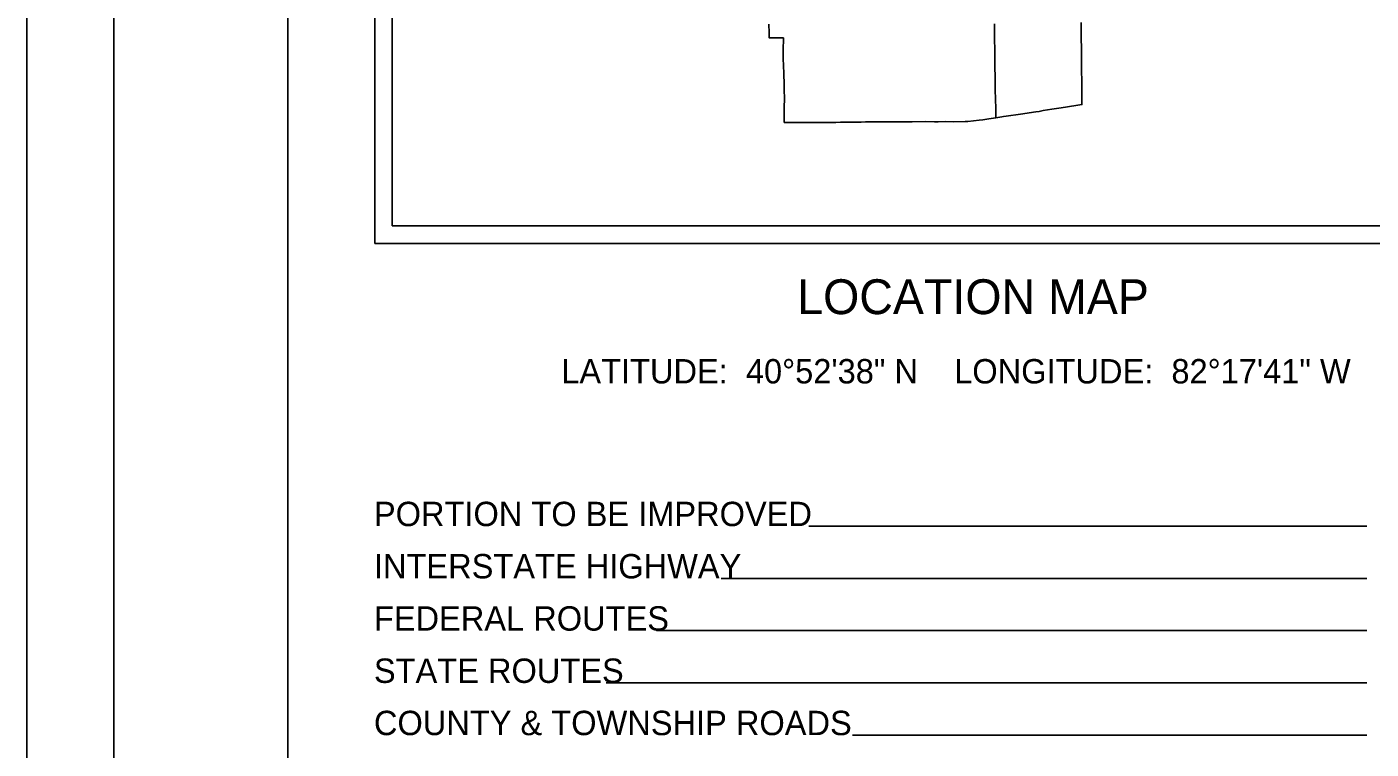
# Model space of a CAD drawing. Extents: x 0 to 34, y 0 to 22.
# Drawn here: x 0 to 7.72, y 11.1 to 15.24 of the extents above; entities that cross this region are included whole.
import ezdxf

# ---------------------------------------------------------------- set-up
doc = ezdxf.new("R2010")
doc.units = 0
for name, color, linetype in [('Default', 7, 'Continuous'), ('SH_Border', 7, 'Continuous'), ('SH_Cut_Line', 7, 'Continuous'), ('SH_Data', 7, 'Continuous'), ('SH_Text', 7, 'Continuous')]:
    doc.layers.add(name, color=color, linetype=linetype)

msp = doc.modelspace()

# ---------------------------------------------------------------- linework, layer by layer
at = {"layer": 'Default'}
for points in [[(5.5601, 15.2613), (5.5609, 15.1865), (5.5611, 15.1717), (5.5618, 15.1118), (5.5619, 15.1041), (5.5633, 15.0252), (5.5641, 14.9432), (5.5654, 14.8865), (5.5668, 14.8216), (5.5678, 14.781), (5.569, 14.7214), (5.529, 14.7152), (5.494, 14.7099), (5.4731, 14.7073), (5.407, 14.6989), (5.3927, 14.6996), (5.3253, 14.6988), (5.2793, 14.6991), (5.2365, 14.6988), (5.2159, 14.6988), (5.1614, 14.6993), (5.0874, 14.6984), (5.0815, 14.6984), (5.0108, 14.6982), (4.9997, 14.6982), (4.9491, 14.6981), (4.8769, 14.6973), (4.8544, 14.6975), (4.8382, 14.6973), (4.8195, 14.697), (4.7947, 14.6965), (4.7775, 14.6963), (4.7771, 14.6962), (4.7749, 14.6961), (4.7433, 14.6958), (4.7087, 14.6954), (4.6757, 14.6952), (4.6487, 14.6949), (4.6274, 14.6945), (4.6186, 14.6941), (4.5945, 14.6941), (4.5837, 14.694), (4.5136, 14.6942), (4.4643, 14.6941), (4.3606, 14.6943), (4.3524, 14.6941), (4.3523, 14.6997), (4.3521, 14.7351), (4.3522, 14.7904), (4.3522, 14.7943), (4.3522, 14.7996), (4.3525, 14.8041), (4.3526, 14.8052), (4.353, 14.8062), (4.3533, 14.8068), (4.3536, 14.8125), (4.3535, 14.8166), (4.3515, 14.8975), (4.3512, 14.9088), (4.3496, 14.9788), (4.348, 15.0176), (4.3462, 15.0638), (4.3462, 15.0896), (4.3461, 15.1058), (4.3463, 15.1081), (4.3475, 15.1798), (4.2898, 15.18), (4.2661, 15.1797), (4.2654, 15.2096), (4.2644, 15.2582)], [(6.0584, 15.2686), (6.0584, 15.2243), (6.0587, 15.1984), (6.0588, 15.1876), (6.0593, 15.1698), (6.0597, 15.1265), (6.0602, 15.0819), (6.0604, 15.0659), (6.0614, 14.9776), (6.0618, 14.9461), (6.0618, 14.9452), (6.0619, 14.9304), (6.0621, 14.9142), (6.0624, 14.8878), (6.063, 14.828), (6.0631, 14.813), (6.0632, 14.7968), (6.0285, 14.7915), (5.9434, 14.778), (5.8908, 14.7697), (5.8403, 14.762), (5.8323, 14.7608), (5.817, 14.758), (5.7973, 14.7553), (5.7107, 14.7418), (5.6282, 14.73), (5.6122, 14.7282), (5.6028, 14.7266), (5.569, 14.7214), (5.5678, 14.781), (5.5668, 14.8216), (5.5654, 14.8865), (5.5641, 14.9432), (5.5633, 15.0252), (5.5619, 15.1041), (5.5618, 15.1118), (5.5611, 15.1717), (5.5609, 15.1865), (5.5601, 15.2613)]]:
    msp.add_lwpolyline(points, dxfattribs=at)
at = {"layer": 'SH_Border'}
for points in [[(0.5, 21.5), (1.5, 21.5), (1.5, 0.5), (0.5, 0.5)], [(1.5, 21.5), (33.5, 21.5), (33.5, 0.5), (1.5, 0.5)]]:
    msp.add_lwpolyline(points, close=True, dxfattribs=at)
at = {"layer": 'SH_Cut_Line'}
msp.add_lwpolyline([(0, 0), (34, 0), (34, 22), (0, 22)], close=True, dxfattribs=at)
at = {"layer": 'SH_Data'}
for p, q in [((2, 21), (2, 14)), ((2.1, 20.9), (2.1, 14.1)), ((2.1, 14.1), (8.9, 14.1)), ((2.1, 14.1), (2.1, 14.1)), ((2, 14), (9, 14)), ((7.7, 12.3767), (4.4937, 12.3767)), ((7.7, 12.0767), (3.9895, 12.0767)), ((7.7, 11.7767), (3.6192, 11.7767)), ((7.7, 11.4767), (3.3288, 11.4767)), ((7.7, 11.1767), (4.7452, 11.1767))]:
    msp.add_line(p, q, dxfattribs=at)

# ---------------------------------------------------------------- texts
at = {"layer": 'SH_Text'}
for s, height, p in [('LOCATION MAP', 0.2, (4.4269, 13.5938)), ('LATITUDE:  40°52\'38" N    LONGITUDE:  82°17\'41" W', 0.14, (3.071, 13.1959)), ('PORTION TO BE IMPROVED', 0.14, (1.9944, 12.3767)), ('INTERSTATE HIGHWAY', 0.14, (1.9944, 12.0767)), ('FEDERAL ROUTES', 0.14, (1.9944, 11.7767)), ('STATE ROUTES', 0.14, (1.9944, 11.4767)), ('COUNTY & TOWNSHIP ROADS', 0.14, (1.9944, 11.1767))]:
    msp.add_text(s, height=height, dxfattribs=at).set_placement(p)

doc.saveas('drawing.dxf')
